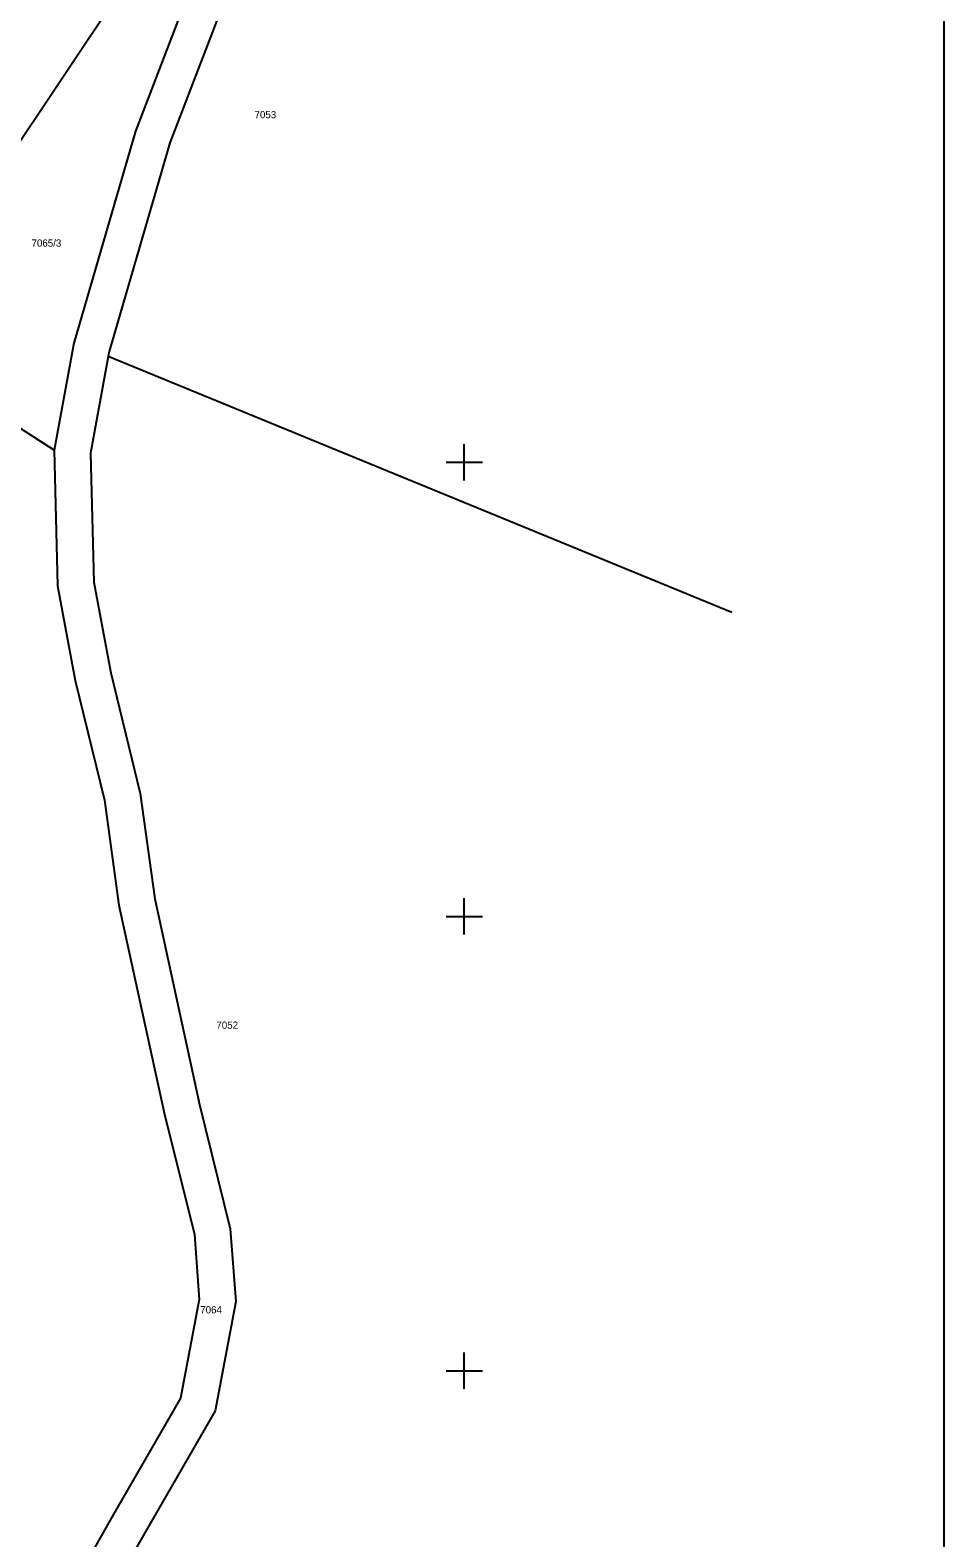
# Model space of a CAD drawing. Extents: x -612546 to -611926, y -1201932 to -1200444.
# Drawn here: x -612047.8 to -611947.2, y -1201768.4 to -1201602.4 of the extents above; entities that cross this region are included whole.
import ezdxf

# ---------------------------------------------------------------- set-up
doc = ezdxf.new("R2010")
doc.units = 0
for name, color, linetype in [('61 legenda křížky', 7, 'Continuous'), ('Hranice parcel', 7, 'Continuous'), ('Parcelní čísla', 7, 'Continuous'), ('Vrstva 63', 7, 'Continuous')]:
    doc.layers.add(name, color=color, linetype=linetype)

msp = doc.modelspace()

# ---------------------------------------------------------------- linework, layer by layer
at = {"layer": '61 legenda křížky'}
for p, q in [((-612000, -1201652), (-612000, -1201648)), ((-612002, -1201650), (-611998, -1201650)), ((-612000, -1201702), (-612000, -1201698)), ((-612002, -1201700), (-611998, -1201700)), ((-612000, -1201752), (-612000, -1201748)), ((-612002, -1201750), (-611998, -1201750))]:
    msp.add_line(p, q, dxfattribs=at)
at = {"layer": 'Hranice parcel'}
for p, q in [((-611970.54, -1201666.56), (-612039.19, -1201638.35)), ((-612045.15, -1201648.68), (-612058.05, -1201640.39))]:
    msp.add_line(p, q, dxfattribs=at)
for points in [[(-611969.89, -1201533.65), (-611997.92, -1201553.23), (-612006.98, -1201560.76), (-612020.6, -1201579.7), (-612029.6, -1201596.32), (-612036.2, -1201613.55), (-612042.99, -1201636.89), (-612045.15, -1201648.68)], [(-611996.06, -1201535.15), (-612001.15, -1201544.98), (-612031.12, -1201588.08), (-612050.83, -1201617.6), (-612058.05, -1201640.39)], [(-611998.56, -1201558.96), (-612004.03, -1201563.51), (-612017.2, -1201581.83), (-612025.96, -1201597.99), (-612032.41, -1201614.83), (-612039.09, -1201637.81), (-612039.19, -1201638.35)], [(-612039.19, -1201638.35), (-612041.14, -1201648.99), (-612040.77, -1201663.19), (-612038.91, -1201673.2), (-612035.67, -1201686.45), (-612034.07, -1201698.06), (-612029.15, -1201720.7), (-612025.75, -1201734.39), (-612025.16, -1201742.39), (-612027.41, -1201754.42), (-612035.16, -1201767.85), (-612039.07, -1201774.7)], [(-612045.15, -1201648.68), (-612044.76, -1201663.61), (-612042.82, -1201674.04), (-612039.6, -1201687.2), (-612038.01, -1201698.76), (-612033.05, -1201721.61), (-612029.71, -1201735.02), (-612029.19, -1201742.16), (-612031.22, -1201753.01), (-612038.64, -1201765.87), (-612042.48, -1201772.61), (-612053.27, -1201789.08), (-612075.33, -1201806.02), (-612095.2, -1201824.86), (-612117.25, -1201850.61), (-612145.1, -1201866.35)]]:
    msp.add_lwpolyline(points, dxfattribs=at)
at = {"layer": 'Vrstva 63'}
msp.add_line((-611947.2, -1201512.06), (-611947.2, -1201932.06), dxfattribs=at)

# ---------------------------------------------------------------- texts
at = {"layer": 'Parcelní čísla'}
for s, p in [('7053', (-612023.08, -1201612.14)), ('7065/3', (-612047.63, -1201626.28)), ('7052', (-612027.28, -1201712.36)), ('7064', (-612029.06, -1201743.69))]:
    msp.add_text(s, height=0.8, dxfattribs=at).set_placement(p)

doc.saveas('drawing.dxf')
